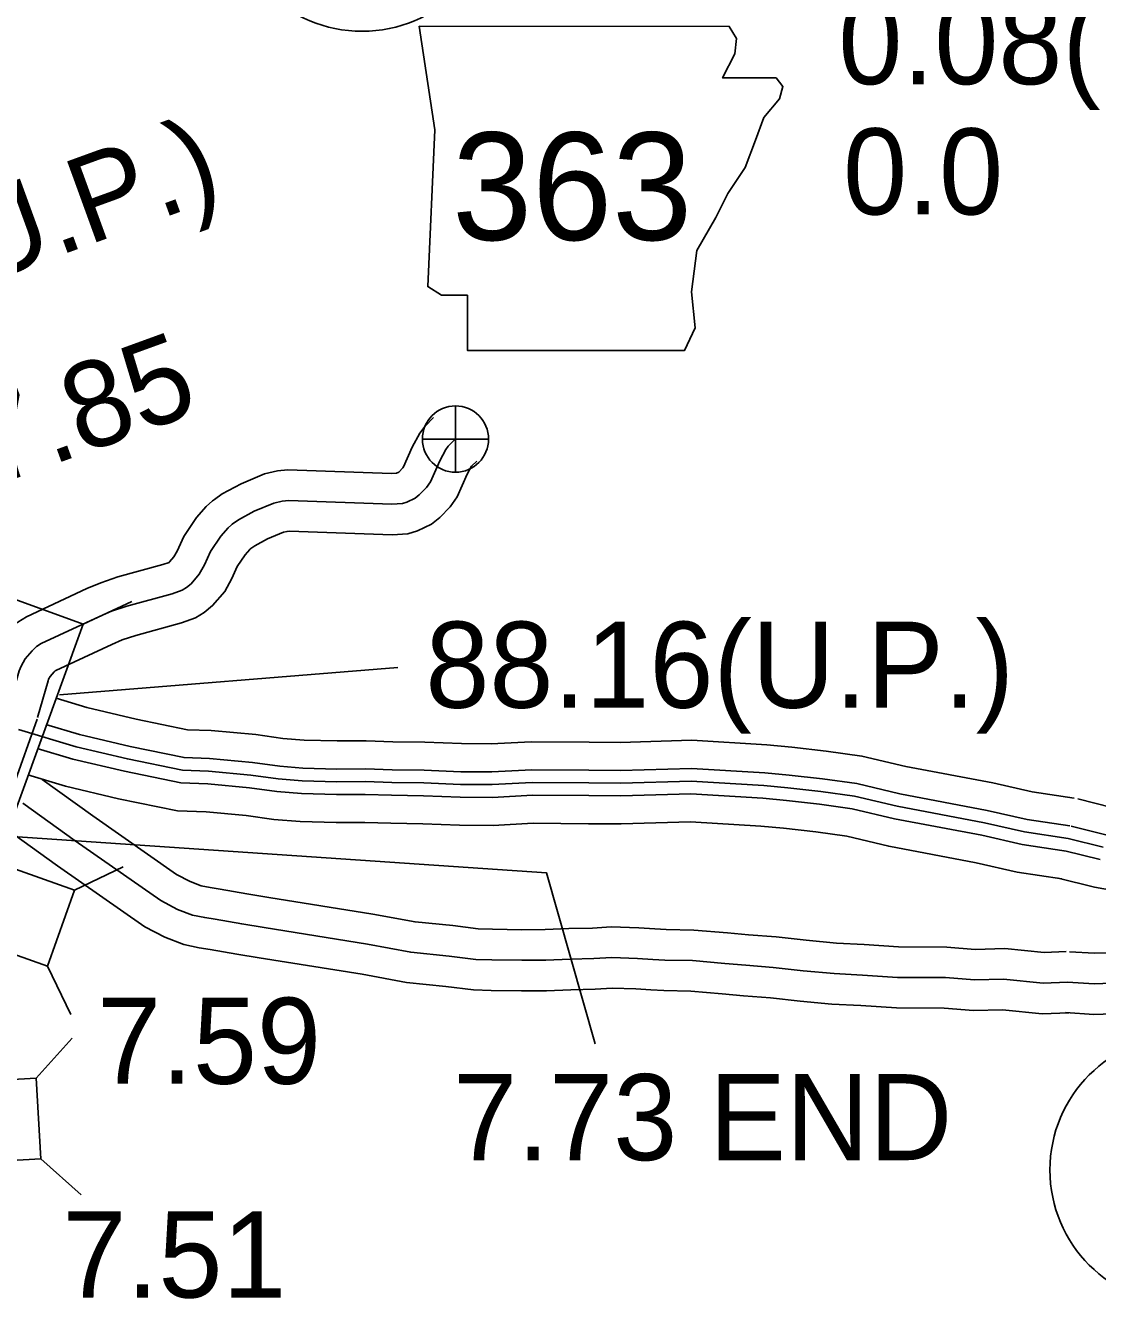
# Model space of a CAD drawing. Extents: x 31699 to 244310, y -8841 to 11474.
# Drawn here: x 97596.7 to 97947.3, y 3576.6 to 3994.9 of the extents above; entities that cross this region are included whole.
import ezdxf

# ---------------------------------------------------------------- set-up
doc = ezdxf.new("R2010")
doc.units = 0
for name, color, linetype in [('B_Logo', 7, 'Continuous'), ('G-ANNO-TEXT', 7, 'Continuous'), ('Level 21', 7, 'Continuous'), ('Level 55', 7, 'Continuous'), ('New Level (0)', 7, 'Continuous'), ('R_Border Notes', 7, 'Continuous'), ('R_XS_EARTHWORK_STAGE1', 7, 'Continuous'), ('R_XS_EARTHWORK_STAGE2', 7, 'Continuous'), ('S_AREA_CALC', 7, 'Continuous'), ('S_WALL', 7, 'Continuous'), ('S_WALL_ANNOT', 7, 'Continuous')]:
    doc.layers.add(name, color=color, linetype=linetype)

msp = doc.modelspace()

# ---------------------------------------------------------------- linework, layer by layer
at = {"layer": 'B_Logo'}
for points in [[(97737.23, 3859.57), (97734.95, 3857.31), (97734.15, 3856.22), (97732.17, 3852.56), (97729.13, 3845.7), (97727.84, 3843.83), (97725.5, 3841.43), (97724.13, 3840.33), (97721.36, 3838.99), (97719.97, 3838.59), (97716.51, 3838.37), (97682.76, 3839.52), (97680.66, 3839.34), (97677.94, 3838.7), (97671.51, 3836.01), (97666.34, 3833.21), (97664.32, 3831.77)], [(97664.32, 3831.77), (97664.05, 3831.58), (97662.94, 3830.58), (97660.6, 3827.89), (97657.19, 3822.86), (97655.19, 3818.53), (97653.53, 3815.48), (97650.84, 3812.3), (97649.37, 3811.1), (97647.96, 3810.26), (97644.69, 3809.04), (97629.82, 3805.01), (97624.8, 3803.31), (97620.84, 3801.65), (97601.82, 3792.76), (97600.28, 3791.79), (97598.81, 3790.41), (97596.54, 3787.78), (97595.2, 3785.41), (97594.57, 3783.82), (97591, 3771.3)], [(97937.7, 3728.98), (97923.51, 3731.12), (97910.36, 3734.11), (97881.86, 3739.52), (97867.83, 3742.83), (97856.89, 3744.37), (97846.02, 3745.58), (97838.22, 3746.29), (97814.43, 3747.75), (97791.39, 3747.08), (97780.94, 3747.16), (97762.42, 3747.28), (97749.31, 3746.6), (97738.99, 3746.68), (97727, 3747.14), (97716.54, 3747.28), (97707.88, 3747.58), (97698.49, 3747.54), (97687.16, 3747.88), (97679.36, 3748.45), (97670.42, 3749.75), (97656.56, 3751), (97648.03, 3751.3), (97630, 3755.03), (97613.24, 3758.97), (97594.39, 3764.63)], [(97937.56, 3681.99), (97929.58, 3681.63), (97916.65, 3682.95), (97907.06, 3682.71), (97897.66, 3683.47), (97881.95, 3683.55), (97870.48, 3684.29), (97861.22, 3684.78), (97851.09, 3685.73), (97841.28, 3686.82), (97832.35, 3687.52), (97825.42, 3688.11), (97814.82, 3689.05), (97805.82, 3689.21), (97801.89, 3689.44), (97796.83, 3689.78), (97788.43, 3690.08), (97782.58, 3689.68), (97774.79, 3689.52), (97766.87, 3689.16), (97759.01, 3689.14), (97749.22, 3689.29), (97744.02, 3689.43), (97735.28, 3690.53), (97722.68, 3691.79), (97708.53, 3694.43), (97674.7, 3699.85), (97667.43, 3701.03), (97658.75, 3702.54), (97655.28, 3703.1), (97651.28, 3703.92), (97646.39, 3705.8), (97640.9, 3708.67), (97612.95, 3728.25), (97595.75, 3740.54)], [(97937.7, 3728.98), (97949.16, 3726.13)], [(97937.56, 3681.99), (97946.29, 3681.4), (97954.61, 3681.75)]]:
    msp.add_lwpolyline(points, dxfattribs=at)
at = {"layer": 'G-ANNO-TEXT'}
msp.add_lwpolyline([(97725.46, 3994.69), (97730.53, 3960.85), (97728.28, 3909.54), (97732.79, 3906.72), (97741.25, 3906.72), (97741.25, 3888.67), (97812.3, 3888.67), (97815.69, 3896), (97814.56, 3907.84), (97816.25, 3921.38), (97822.45, 3932.09), (97826.4, 3939.99), (97832.04, 3948.45), (97835.42, 3957.47), (97838.24, 3964.8), (97843.32, 3971), (97844.45, 3974.95), (97842.19, 3977.77), (97824.71, 3977.77), (97828.66, 3985.67), (97829.22, 3990.74), (97826.88, 3994.64)], close=True, dxfattribs=at)
at = {"layer": 'Level 21'}
for p, q in [((97737.33, 3848.82), (97737.33, 3870.48)), ((97726.49, 3859.65), (97748.16, 3859.65))]:
    msp.add_line(p, q, dxfattribs=at)
msp.add_circle((97737.33, 3859.65), 10.83, dxfattribs=at)
at = {"layer": 'Level 55'}
for points in [[(97730.19, 3866.66), (97727.37, 3863.87), (97725.69, 3861.6), (97723.18, 3856.97), (97720.37, 3850.6), (97720.09, 3850.2), (97718.77, 3848.85), (97718.75, 3848.83), (97718.03, 3848.48), (97716.37, 3848.38), (97682.49, 3849.54), (97679.08, 3849.24), (97674.85, 3848.25), (97667.18, 3845.04), (97661.05, 3841.71), (97658.53, 3839.93)], [(97744.28, 3852.47), (97742.58, 3850.78), (97741.15, 3848.15), (97737.9, 3840.79), (97735.59, 3837.45), (97732.23, 3834.01), (97729.5, 3831.82), (97724.95, 3829.62), (97721.69, 3828.68), (97716.65, 3828.36), (97683.02, 3829.51), (97682.24, 3829.44), (97681.03, 3829.16), (97675.84, 3826.98), (97671.64, 3824.7), (97670.1, 3823.62)], [(97658.53, 3839.93), (97657.79, 3839.4), (97655.79, 3837.6), (97652.66, 3833.99), (97648.46, 3827.79), (97646.25, 3823.02), (97645.24, 3821.16), (97643.8, 3819.46), (97643.63, 3819.32), (97641.63, 3818.58), (97626.91, 3814.58), (97621.26, 3812.67), (97616.78, 3810.79), (97597.02, 3801.55), (97594.14, 3799.74), (97591.59, 3797.35), (97588.32, 3793.57), (97586.15, 3789.74), (97585.09, 3787.04), (97581.38, 3774.04)], [(97670.3, 3823.76), (97670.09, 3823.56), (97668.55, 3821.79), (97665.93, 3817.92), (97664.14, 3814.04), (97661.83, 3809.79), (97657.89, 3805.15), (97655.12, 3802.88), (97652.28, 3801.2), (97647.75, 3799.51), (97632.73, 3795.43), (97628.34, 3793.95), (97624.9, 3792.5), (97606.62, 3783.97), (97606.42, 3783.84), (97606.03, 3783.48), (97604.75, 3782), (97604.24, 3781.08), (97604.05, 3780.6), (97600.62, 3768.56)], [(97600.43, 3767.98), (97592.79, 3746.25)]]:
    msp.add_lwpolyline(points, dxfattribs=at)
at = {"layer": 'New Level (0)'}
for points in [[(97939.69, 3742.16), (97925.99, 3744.23), (97913.08, 3747.16), (97884.63, 3752.56), (97870.3, 3755.95), (97858.56, 3757.6), (97847.36, 3758.85), (97839.23, 3759.59), (97814.64, 3761.1), (97791.25, 3760.42), (97781.03, 3760.5), (97762.12, 3760.62), (97749.01, 3759.93), (97739.3, 3760.01), (97727.35, 3760.47), (97716.86, 3760.61), (97708.08, 3760.92), (97698.66, 3760.88), (97687.85, 3761.2), (97680.82, 3761.72), (97671.98, 3763), (97657.39, 3764.31), (97649.63, 3764.58), (97632.88, 3768.05), (97616.69, 3771.86), (97606.71, 3774.85)], [(97938.32, 3733.1), (97924.29, 3735.22), (97911.21, 3738.18), (97882.72, 3743.59), (97868.6, 3746.93), (97857.41, 3748.5), (97846.44, 3749.73), (97838.54, 3750.45), (97814.49, 3751.92), (97791.35, 3751.25), (97780.97, 3751.33), (97762.33, 3751.45), (97749.22, 3750.76), (97739.08, 3750.84), (97727.1, 3751.3), (97716.64, 3751.45), (97707.94, 3751.75), (97698.54, 3751.71), (97687.38, 3752.04), (97679.82, 3752.6), (97670.91, 3753.89), (97656.82, 3755.16), (97648.53, 3755.45), (97630.9, 3759.1), (97614.32, 3763), (97603.32, 3766.3)], [(97937.08, 3724.86), (97922.74, 3727.02), (97909.51, 3730.03), (97880.99, 3735.44), (97867.06, 3738.73), (97856.37, 3740.24), (97845.6, 3741.43), (97837.9, 3742.14), (97814.36, 3743.58), (97791.44, 3742.92), (97780.91, 3743), (97762.52, 3743.11), (97749.4, 3742.43), (97738.89, 3742.51), (97726.89, 3742.97), (97716.44, 3743.12), (97707.81, 3743.42), (97698.44, 3743.37), (97686.95, 3743.72), (97678.91, 3744.31), (97669.94, 3745.61), (97656.3, 3746.84), (97647.53, 3747.15), (97629.1, 3750.96), (97612.16, 3754.95), (97600.43, 3758.47)], [(97935.71, 3715.79), (97921.04, 3718.01), (97907.64, 3721.05), (97879.08, 3726.47), (97865.36, 3729.71), (97855.22, 3731.14), (97844.68, 3732.31), (97837.21, 3732.99), (97814.21, 3734.41), (97791.54, 3733.75), (97780.84, 3733.83), (97762.73, 3733.95), (97749.61, 3733.26), (97738.68, 3733.34), (97726.65, 3733.81), (97716.21, 3733.95), (97707.68, 3734.25), (97698.32, 3734.21), (97686.47, 3734.56), (97677.91, 3735.19), (97668.87, 3736.51), (97655.73, 3737.68), (97646.43, 3738.01), (97627.12, 3742.01), (97609.79, 3746.09), (97597.45, 3749.79)], [(97940.92, 3741.92), (97952, 3739.17)], [(97938.71, 3733.02), (97950.05, 3730.21)], [(97936.7, 3724.93), (97948.27, 3722.06)], [(97934.49, 3716.04), (97946.33, 3713.1), (97954.35, 3711.59)]]:
    msp.add_lwpolyline(points, dxfattribs=at)
at = {"layer": 'R_Border Notes'}
for centre in [(97706.78, 4037.05), (97975.79, 3620.56)]:
    msp.add_circle(centre, 44, dxfattribs=at)
at = {"layer": 'R_XS_EARTHWORK_STAGE1'}
for p, q in [((97615.52, 3799.09), (97631.47, 3806.54)), ((97612.71, 3712.13), (97628.6, 3719.7)), ((97603.89, 3687.24), (97611.46, 3671.36)), ((97600.21, 3650.54), (97611.93, 3663.67)), ((97601.7, 3624.18), (97614.83, 3612.46))]:
    msp.add_line(p, q, dxfattribs=at)
for points in [[(97588.49, 3724.65), (97615.52, 3799.09), (97590.71, 3808.1), (97563.67, 3733.66)], [(97529.24, 3713.71), (97603.89, 3687.24), (97612.71, 3712.13), (97538.06, 3738.59)], [(97522.63, 3619.71), (97601.7, 3624.18), (97600.21, 3650.54), (97521.14, 3646.06)]]:
    msp.add_lwpolyline(points, close=True, dxfattribs=at)
at = {"layer": 'R_XS_EARTHWORK_STAGE2'}
msp.add_lwpolyline([(97783.07, 3661.86), (97767.1, 3717.8), (97576.4, 3730.78)], dxfattribs=at)
at = {"layer": 'S_AREA_CALC'}
for points in [[(97937.13, 3691.98), (97929.87, 3691.66), (97917.03, 3692.97), (97907.34, 3692.72), (97898.09, 3693.47), (97882.29, 3693.55), (97871.07, 3694.27), (97861.95, 3694.76), (97852.1, 3695.68), (97842.22, 3696.78), (97833.16, 3697.49), (97826.28, 3698.07), (97815.35, 3699.04), (97806.2, 3699.21), (97802.51, 3699.42), (97797.34, 3699.77), (97788.27, 3700.09), (97782.13, 3699.67), (97774.46, 3699.52), (97766.62, 3699.16), (97759.07, 3699.14), (97749.43, 3699.29), (97744.78, 3699.42), (97736.41, 3700.47), (97724.1, 3701.7), (97710.24, 3704.28), (97676.3, 3709.72), (97669.08, 3710.89), (97660.4, 3712.4), (97657.09, 3712.93), (97654.1, 3713.55), (97650.52, 3714.92), (97646.1, 3717.23), (97618.73, 3736.41), (97602.15, 3748.26)], [(97938, 3671.99), (97929.29, 3671.61), (97916.27, 3672.94), (97906.79, 3672.7), (97897.23, 3673.47), (97881.6, 3673.56), (97869.9, 3674.31), (97860.49, 3674.81), (97850.07, 3675.78), (97840.34, 3676.86), (97831.54, 3677.55), (97824.55, 3678.14), (97814.28, 3679.06), (97805.45, 3679.22), (97801.27, 3679.46), (97796.31, 3679.79), (97788.59, 3680.07), (97783.02, 3679.69), (97775.11, 3679.53), (97767.11, 3679.16), (97758.95, 3679.14), (97749, 3679.29), (97743.26, 3679.45), (97734.16, 3680.6), (97721.27, 3681.88), (97706.82, 3684.58), (97673.11, 3689.98), (97665.77, 3691.17), (97657.1, 3692.67), (97653.48, 3693.26), (97648.46, 3694.29), (97642.26, 3696.67), (97635.69, 3700.11), (97607.18, 3720.09), (97589.99, 3732.37)], [(97938.23, 3691.96), (97946.41, 3691.42), (97954.05, 3691.74), (97961.73, 3692.28), (97965.87, 3692.6), (97978.5, 3694.13), (97984.35, 3694.93), (97990.83, 3695.89), (98000, 3697.86), (98008.65, 3699.52), (98011.8, 3700.3), (98015.87, 3701.71), (98023.38, 3703.54), (98026.33, 3704.35)], [(97936.9, 3672.01), (97946.17, 3671.39), (97955.17, 3671.77)]]:
    msp.add_lwpolyline(points, dxfattribs=at)
at = {"layer": 'S_WALL'}
msp.add_lwpolyline([(97718.52, 3784.96), (97607.77, 3775.98)], dxfattribs=at)

# ---------------------------------------------------------------- texts
at = {"layer": 'G-ANNO-TEXT'}
msp.add_text('363', height=35.2, dxfattribs=at).set_placement((97736.24, 3924.76))
at = {"layer": 'S_WALL'}
for s, height, p in [('0.08(O.P.)', 28.16, (97862.57, 3975.73)), ('88.16(U.P.)', 28.1599, (97727.49, 3771.74)), ('7.59', 28.16, (97620.05, 3648.73)), ('7.51', 28.16, (97608.74, 3578.81))]:
    msp.add_text(s, height=height, dxfattribs=at).set_placement(p)
for s, height, p in [('87.04(U.P.)', 28.1599, (97481.31, 3873.58)), ('87.85', 28.16, (97565.83, 3836.7))]:
    msp.add_text(s, height=height, rotation=20, dxfattribs=at).set_placement(p)
at = {"layer": 'S_WALL_ANNOT'}
for s, p in [('0.0', (97864.13, 3933.12)), ('7.73 END', (97736.59, 3623.75))]:
    msp.add_text(s, height=28.16, dxfattribs=at).set_placement(p)

doc.saveas('drawing.dxf')
